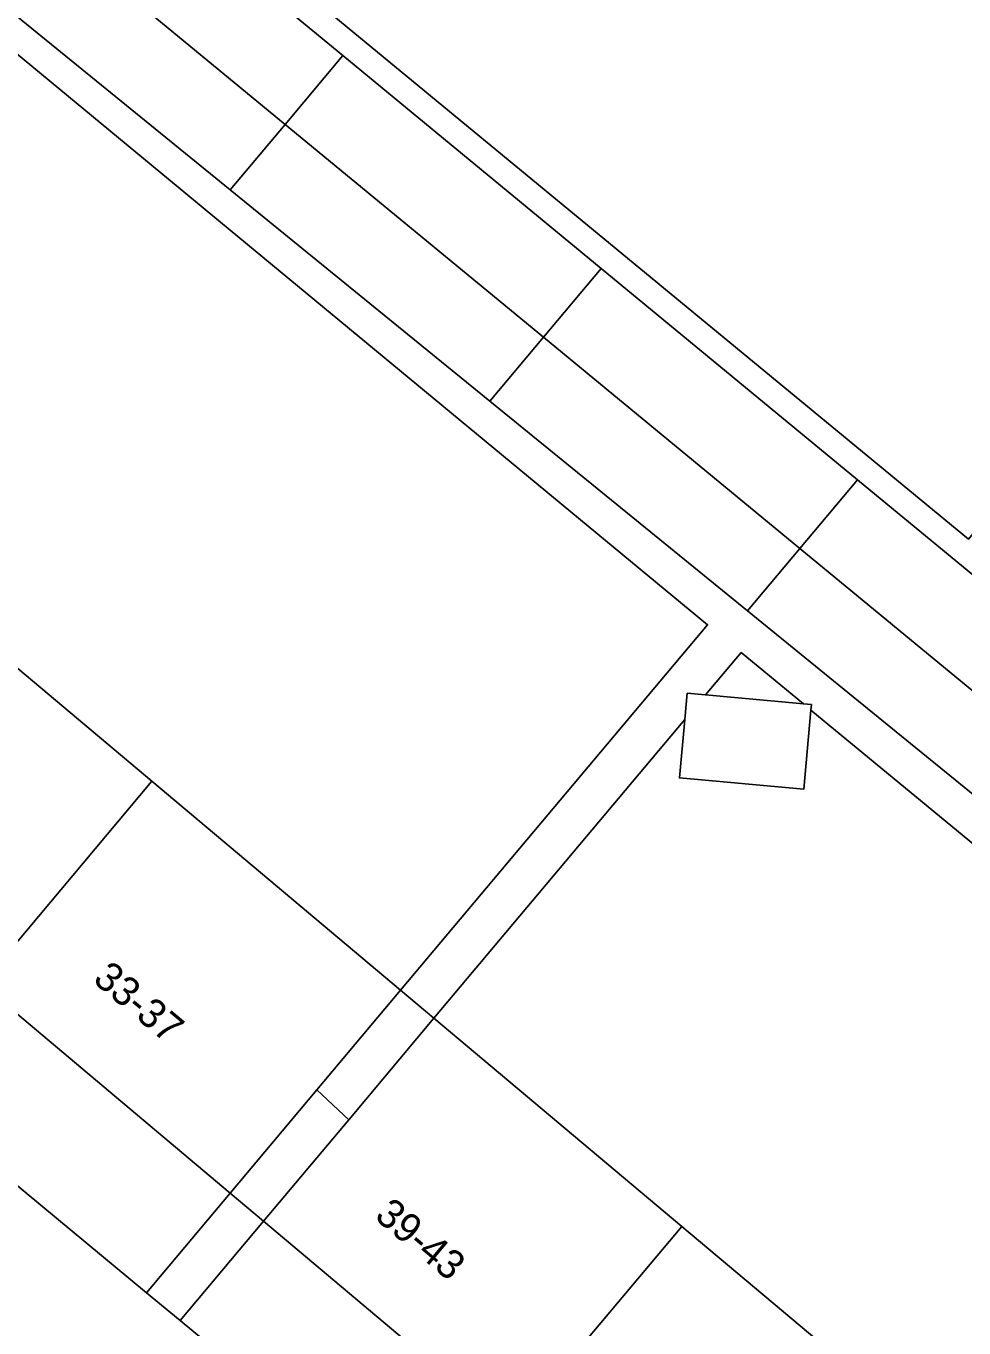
# Model space of a CAD drawing. Extents: x 162074 to 163034, y 381824 to 382557.
# Drawn here: x 162472.44 to 162504.71, y 382141.55 to 382186.32 of the extents above; entities that cross this region are included whole.
import ezdxf

# ---------------------------------------------------------------- set-up
doc = ezdxf.new("R2010")
doc.units = 0
for name, color, linetype in [('IMGEO_Pand', 7, 'Continuous'), ('IMGEO_Pand_nummerreeks', 7, 'Continuous'), ('IMGEO_Pand_overbouw', 7, 'Continuous'), ('IMGEO_Voetpad_open', 7, 'Continuous')]:
    doc.layers.add(name, color=color, linetype=linetype)

msp = doc.modelspace()

# ---------------------------------------------------------------- linework, layer by layer
at = {"layer": 'IMGEO_Pand'}
for points in [[(162474.834, 382192.306), (162483.342, 382185.3)], [(162472.847, 382189.941), (162481.355, 382182.935)], [(162479.465, 382180.685), (162470.913, 382187.639)], [(162483.342, 382185.3), (162481.355, 382182.935)], [(162483.342, 382185.3), (162492.233, 382177.98)], [(162479.465, 382180.685), (162481.355, 382182.935)], [(162481.355, 382182.935), (162490.246, 382175.614)], [(162488.401, 382173.417), (162479.465, 382180.685)], [(162492.233, 382177.98), (162490.246, 382175.614)], [(162492.233, 382177.98), (162501.052, 382170.717)], [(162488.401, 382173.417), (162490.246, 382175.614)], [(162490.246, 382175.614), (162499.065, 382168.351)], [(162497.266, 382166.209), (162488.401, 382173.417)], [(162501.052, 382170.717), (162499.065, 382168.351)], [(162501.052, 382170.717), (162510.617, 382162.841)], [(162499.065, 382168.351), (162497.266, 382166.209)], [(162499.065, 382168.351), (162508.63, 382160.476)], [(162468.337, 382167.44), (162476.774, 382160.352)], [(162506.878, 382158.391), (162497.266, 382166.209)], [(162495.107, 382162.468), (162495.19, 382163.374), (162495.821, 382163.317)], [(162495.821, 382163.317), (162499.19, 382163.01)], [(162495.107, 382162.468), (162494.925, 382160.465), (162499.201, 382160.076), (162499.448, 382162.798)], [(162499.19, 382163.01), (162499.465, 382162.985), (162499.448, 382162.798)], [(162470.908, 382153.37), (162476.774, 382160.352)], [(162476.774, 382160.352), (162485.329, 382153.165)], [(162479.463, 382146.183), (162470.908, 382153.37)], [(162485.329, 382153.165), (162482.446, 382149.734), (162479.463, 382146.183)], [(162480.612, 382145.218), (162483.545, 382148.71), (162486.477, 382152.2)], [(162495.005, 382145.036), (162486.477, 382152.2)], [(162480.612, 382145.218), (162489.139, 382138.054)], [(162489.139, 382138.054), (162495.005, 382145.036)], [(162495.005, 382145.036), (162500, 382140.839), (162503.442, 382137.947)]]:
    msp.add_lwpolyline(points, dxfattribs=at)
at = {"layer": 'IMGEO_Pand_overbouw'}
for points in [[(162486.477, 382152.2), (162485.329, 382153.165), (162482.446, 382149.734), (162483.545, 382148.71)], [(162483.545, 382148.71), (162482.446, 382149.734), (162479.463, 382146.183), (162480.612, 382145.218)]]:
    msp.add_lwpolyline(points, close=True, dxfattribs=at)
at = {"layer": 'IMGEO_Voetpad_open'}
for points in [[(162449.439, 382213.218), (162449.979, 382213.874), (162504.869, 382168.675), (162514.495, 382180.304)], [(162485.329, 382153.165), (162495.889, 382165.728), (162452.706, 382201.422)], [(162495.821, 382163.317), (162497.047, 382164.775), (162499.19, 382163.01)], [(162499.448, 382162.798), (162556.67, 382115.671), (162546.719, 382103.588)], [(162486.477, 382152.2), (162495.107, 382162.468)], [(162460.487, 382156.099), (162476.592, 382142.764)], [(162479.463, 382146.183), (162476.592, 382142.764)], [(162477.748, 382141.807), (162480.612, 382145.218)], [(162476.592, 382142.764), (162477.748, 382141.807)], [(162496.281, 382126.462), (162477.748, 382141.807)]]:
    msp.add_lwpolyline(points, dxfattribs=at)

# ---------------------------------------------------------------- texts
at = {"layer": 'IMGEO_Pand_nummerreeks'}
for s, rotation, p in [('33-37', 319.9661, (162474.704, 382153.472)), ('39-43', 319.9617, (162484.394, 382145.332))]:
    msp.add_text(s, height=1, rotation=rotation, dxfattribs=at).set_placement(p)

doc.saveas('drawing.dxf')
